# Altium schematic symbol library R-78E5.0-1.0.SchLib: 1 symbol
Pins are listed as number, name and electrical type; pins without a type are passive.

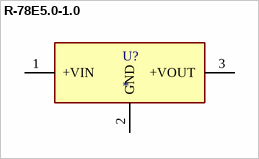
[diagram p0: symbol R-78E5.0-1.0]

## R-78E5.0-1.0
designator U?
1A DC/DC-Converter SIP3; MF: Recom Power; MP: R-78E5.0-1.0
footprint R-78E5.0-1.0
pins: 1 +VIN (power), 2 GND (power), 3 +VOUT (power)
